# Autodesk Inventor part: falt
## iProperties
Created: 2004-11
Part Number: falt
Document SubType Name: Modeling
Designer: jwagner
Manufacturer: Standard
Standards Organization: Custom
Author: jwagner
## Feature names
1. Extrusion1
